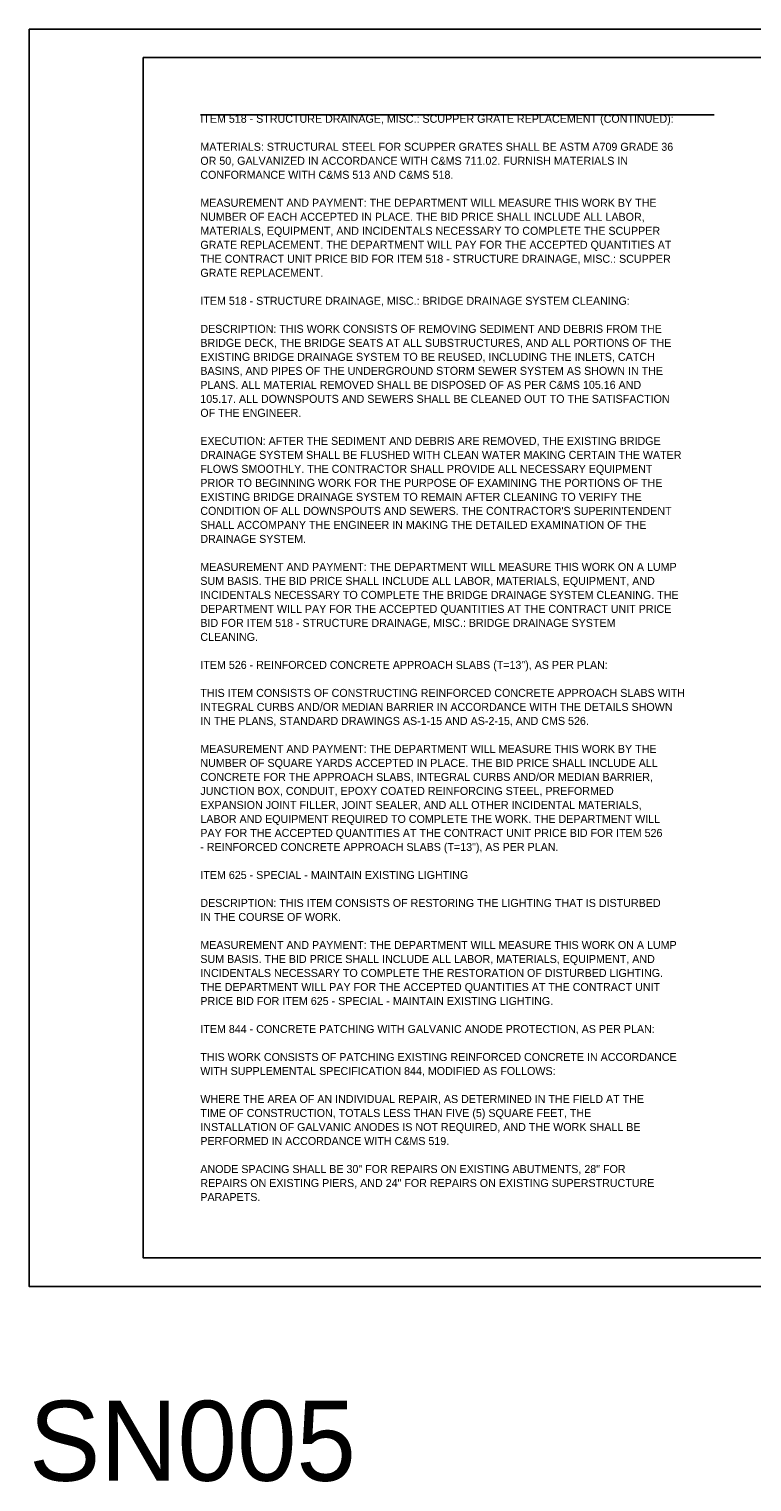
# Model space of a CAD drawing. Extents: x 0 to 72, y -26 to 50.
# Drawn here: x 0 to 12.66, y -3.42 to 22 of the extents above; entities that cross this region are included whole.
import ezdxf

# ---------------------------------------------------------------- set-up
doc = ezdxf.new("R2010")
doc.units = 0
doc.layers.add('SH_Cut_Line', color=7, linetype='Continuous')
doc.layers.add('SH_Data', color=7, linetype='Continuous')

msp = doc.modelspace()

# ---------------------------------------------------------------- linework, layer by layer
at = {"layer": 'SH_Cut_Line'}
msp.add_line((3, 20.5), (12, 20.5), dxfattribs=at)
for points in [[(0, 22), (34, 22), (34, 0), (0, 0)], [(2, 21.5), (32.5, 21.5), (32.5, 0.5), (2, 0.5)]]:
    msp.add_lwpolyline(points, close=True, dxfattribs=at)

# ---------------------------------------------------------------- texts
at = {"layer": 'SH_Data'}
for s, height, p in [('ITEM 518 - STRUCTURE DRAINAGE, MISC.: SCUPPER GRATE REPLACEMENT (CONTINUED): ', 0.14, (3, 20.36)), ('ITEM 518 - STRUCTURE DRAINAGE, MISC.: SCUPPER GRATE REPLACEMENT (CONTINUED):', 0.14, (3, 20.36)), ('MATERIALS: STRUCTURAL STEEL FOR SCUPPER GRATES SHALL BE ASTM A709 GRADE 36 ', 0.14, (3, 19.87)), ('OR 50, GALVANIZED IN ACCORDANCE WITH C&MS 711.02. FURNISH MATERIALS IN ', 0.14, (3, 19.625)), ('CONFORMANCE WITH C&MS 513 AND C&MS 518.', 0.14, (3, 19.38)), ('MEASUREMENT AND PAYMENT: THE DEPARTMENT WILL MEASURE THIS WORK BY THE ', 0.14, (3, 18.89)), ('NUMBER OF EACH ACCEPTED IN PLACE. THE BID PRICE SHALL INCLUDE ALL LABOR, ', 0.14, (3, 18.645)), ('MATERIALS, EQUIPMENT, AND INCIDENTALS NECESSARY TO COMPLETE THE SCUPPER ', 0.14, (3, 18.4)), ('THE CONTRACT UNIT PRICE BID FOR ITEM 518 - STRUCTURE DRAINAGE, MISC.: SCUPPER ', 0.14, (3, 17.91)), ('GRATE REPLACEMENT. THE DEPARTMENT WILL PAY FOR THE ACCEPTED QUANTITIES AT ', 0.14, (3, 18.155)), ('GRATE REPLACEMENT.', 0.14, (3, 17.665)), ('ITEM 518 - STRUCTURE DRAINAGE, MISC.: BRIDGE DRAINAGE SYSTEM CLEANING:', 0.14, (3, 17.175)), ('ITEM 518 - STRUCTURE DRAINAGE, MISC.: BRIDGE DRAINAGE SYSTEM CLEANING:', 0.14, (3, 17.175)), ('DESCRIPTION: THIS WORK CONSISTS OF REMOVING SEDIMENT AND DEBRIS FROM THE ', 0.14, (3, 16.685)), ('BRIDGE DECK, THE BRIDGE SEATS AT ALL SUBSTRUCTURES, AND ALL PORTIONS OF THE ', 0.14, (3, 16.44)), ('EXISTING BRIDGE DRAINAGE SYSTEM TO BE REUSED, INCLUDING THE INLETS, CATCH ', 0.14, (3, 16.195)), ('BASINS, AND PIPES OF THE UNDERGROUND STORM SEWER SYSTEM AS SHOWN IN THE ', 0.14, (3, 15.95)), ('PLANS. ALL MATERIAL REMOVED SHALL BE DISPOSED OF AS PER C&MS 105.16 AND ', 0.14, (3, 15.705)), ('105.17. ALL DOWNSPOUTS AND SEWERS SHALL BE CLEANED OUT TO THE SATISFACTION ', 0.14, (3, 15.46)), ('OF THE ENGINEER. ', 0.14, (3, 15.215)), ('EXECUTION: AFTER THE SEDIMENT AND DEBRIS ARE REMOVED, THE EXISTING BRIDGE ', 0.14, (3, 14.725)), ('DRAINAGE SYSTEM SHALL BE FLUSHED WITH CLEAN WATER MAKING CERTAIN THE WATER ', 0.14, (3, 14.48)), ('FLOWS SMOOTHLY. THE CONTRACTOR SHALL PROVIDE ALL NECESSARY EQUIPMENT ', 0.14, (3, 14.235)), ('PRIOR TO BEGINNING WORK FOR THE PURPOSE OF EXAMINING THE PORTIONS OF THE ', 0.14, (3, 13.99)), ('EXISTING BRIDGE DRAINAGE SYSTEM TO REMAIN AFTER CLEANING TO VERIFY THE ', 0.14, (3, 13.745)), ("CONDITION OF ALL DOWNSPOUTS AND SEWERS. THE CONTRACTOR'S SUPERINTENDENT ", 0.14, (3, 13.5)), ('SHALL ACCOMPANY THE ENGINEER IN MAKING THE DETAILED EXAMINATION OF THE ', 0.14, (3, 13.255)), ('DRAINAGE SYSTEM. ', 0.14, (3, 13.01)), ('MEASUREMENT AND PAYMENT: THE DEPARTMENT WILL MEASURE THIS WORK ON A LUMP ', 0.14, (3, 12.52)), ('SUM BASIS. THE BID PRICE SHALL INCLUDE ALL LABOR, MATERIALS, EQUIPMENT, AND ', 0.14, (3, 12.275)), ('INCIDENTALS NECESSARY TO COMPLETE THE BRIDGE DRAINAGE SYSTEM CLEANING. THE ', 0.14, (3, 12.03)), ('DEPARTMENT WILL PAY FOR THE ACCEPTED QUANTITIES AT THE CONTRACT UNIT PRICE ', 0.14, (3, 11.785)), ('BID FOR ITEM 518 - STRUCTURE DRAINAGE, MISC.: BRIDGE DRAINAGE SYSTEM ', 0.14, (3, 11.54)), ('CLEANING.', 0.14, (3, 11.295)), ('ITEM 526 - REINFORCED CONCRETE APPROACH SLABS (T=13"), AS PER PLAN:', 0.14, (3, 10.805)), ('ITEM 526 - REINFORCED CONCRETE APPROACH SLABS (T=13"), AS PER PLAN:', 0.14, (3, 10.805)), ('THIS ITEM CONSISTS OF CONSTRUCTING REINFORCED CONCRETE APPROACH SLABS WITH ', 0.14, (3, 10.315)), ('INTEGRAL CURBS AND/OR MEDIAN BARRIER IN ACCORDANCE WITH THE DETAILS SHOWN ', 0.14, (3, 10.07)), ('IN THE PLANS, STANDARD DRAWINGS AS-1-15 AND AS-2-15, AND CMS 526.', 0.14, (3, 9.825)), ('MEASUREMENT AND PAYMENT: THE DEPARTMENT WILL MEASURE THIS WORK BY THE ', 0.14, (3, 9.335)), ('NUMBER OF SQUARE YARDS ACCEPTED IN PLACE. THE BID PRICE SHALL INCLUDE ALL ', 0.14, (3, 9.09)), ('CONCRETE FOR THE APPROACH SLABS, INTEGRAL CURBS AND/OR MEDIAN BARRIER, ', 0.14, (3, 8.845)), ('JUNCTION BOX, CONDUIT, EPOXY COATED REINFORCING STEEL, PREFORMED ', 0.14, (3, 8.6)), ('EXPANSION JOINT FILLER, JOINT SEALER, AND ALL OTHER INCIDENTAL MATERIALS, ', 0.14, (3, 8.355)), ('LABOR AND EQUIPMENT REQUIRED TO COMPLETE THE WORK. THE DEPARTMENT WILL ', 0.14, (3, 8.11)), ('PAY FOR THE ACCEPTED QUANTITIES AT THE CONTRACT UNIT PRICE BID FOR ITEM 526 ', 0.14, (3, 7.865)), ('- REINFORCED CONCRETE APPROACH SLABS (T=13"), AS PER PLAN.', 0.14, (3, 7.62)), ('ITEM 625 - SPECIAL - MAINTAIN EXISTING LIGHTING', 0.14, (3, 7.13)), ('ITEM 625 - SPECIAL - MAINTAIN EXISTING LIGHTING', 0.14, (3, 7.13)), ('DESCRIPTION: THIS ITEM CONSISTS OF RESTORING THE LIGHTING THAT IS DISTURBED ', 0.14, (3, 6.64)), ('IN THE COURSE OF WORK.', 0.14, (3, 6.395)), ('MEASUREMENT AND PAYMENT: THE DEPARTMENT WILL MEASURE THIS WORK ON A LUMP ', 0.14, (3, 5.905)), ('SUM BASIS. THE BID PRICE SHALL INCLUDE ALL LABOR, MATERIALS, EQUIPMENT, AND ', 0.14, (3, 5.66)), ('INCIDENTALS NECESSARY TO COMPLETE THE RESTORATION OF DISTURBED LIGHTING. ', 0.14, (3, 5.415)), ('THE DEPARTMENT WILL PAY FOR THE ACCEPTED QUANTITIES AT THE CONTRACT UNIT ', 0.14, (3, 5.17)), ('PRICE BID FOR ITEM 625 - SPECIAL - MAINTAIN EXISTING LIGHTING.', 0.14, (3, 4.925)), ('ITEM 844 - CONCRETE PATCHING WITH GALVANIC ANODE PROTECTION, AS PER PLAN:', 0.14, (3, 4.435)), ('ITEM 844 - CONCRETE PATCHING WITH GALVANIC ANODE PROTECTION, AS PER PLAN:', 0.14, (3, 4.435)), ('THIS WORK CONSISTS OF PATCHING EXISTING REINFORCED CONCRETE IN ACCORDANCE ', 0.14, (3, 3.945)), ('WITH SUPPLEMENTAL SPECIFICATION 844, MODIFIED AS FOLLOWS: ', 0.14, (3, 3.7)), ('WHERE THE AREA OF AN INDIVIDUAL REPAIR, AS DETERMINED IN THE FIELD AT THE ', 0.14, (3, 3.21)), ('TIME OF CONSTRUCTION, TOTALS LESS THAN FIVE (5) SQUARE FEET, THE ', 0.14, (3, 2.965)), ('INSTALLATION OF GALVANIC ANODES IS NOT REQUIRED, AND THE WORK SHALL BE ', 0.14, (3, 2.72)), ('PERFORMED IN ACCORDANCE WITH C&MS 519. ', 0.14, (3, 2.475)), ('ANODE SPACING SHALL BE 30" FOR REPAIRS ON EXISTING ABUTMENTS, 28" FOR ', 0.14, (3, 1.985)), ('REPAIRS ON EXISTING PIERS, AND 24" FOR REPAIRS ON EXISTING SUPERSTRUCTURE ', 0.14, (3, 1.74)), ('PARAPETS.', 0.14, (3, 1.495)), ('SN005', 1.4, (0, -3.4))]:
    msp.add_text(s, height=height, dxfattribs=at).set_placement(p)

doc.saveas('drawing.dxf')
